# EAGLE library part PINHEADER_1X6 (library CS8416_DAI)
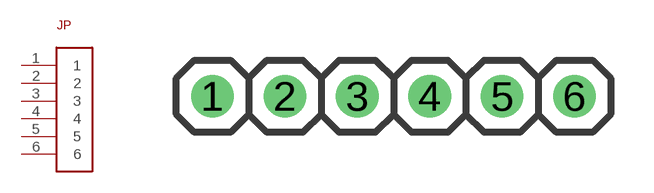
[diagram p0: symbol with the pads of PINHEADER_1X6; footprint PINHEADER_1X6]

Designator prefix JP

## PINHEADER_1X6  [PINHEADER_1X6]
1  1  pas
2  2  pas
3  3  pas
4  4  pas
5  5  pas
6  6  pas

## Footprint PINHEADER_1X6 (pad centres in mm)
drill 0.991 round: 1 -7.62,0; 2 -5.08,0; 3 -2.54,0; 4 0,0; 5 2.54,0; 6 5.08,0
